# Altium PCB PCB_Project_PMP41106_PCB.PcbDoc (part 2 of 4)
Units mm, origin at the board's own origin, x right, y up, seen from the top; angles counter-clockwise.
Board outline 190 x 100 mm, 2 copper layers (Top Layer, Bottom Layer), stack 1.646 mm thick; 219 components, 122 nets, 541 pads, 61 vias.
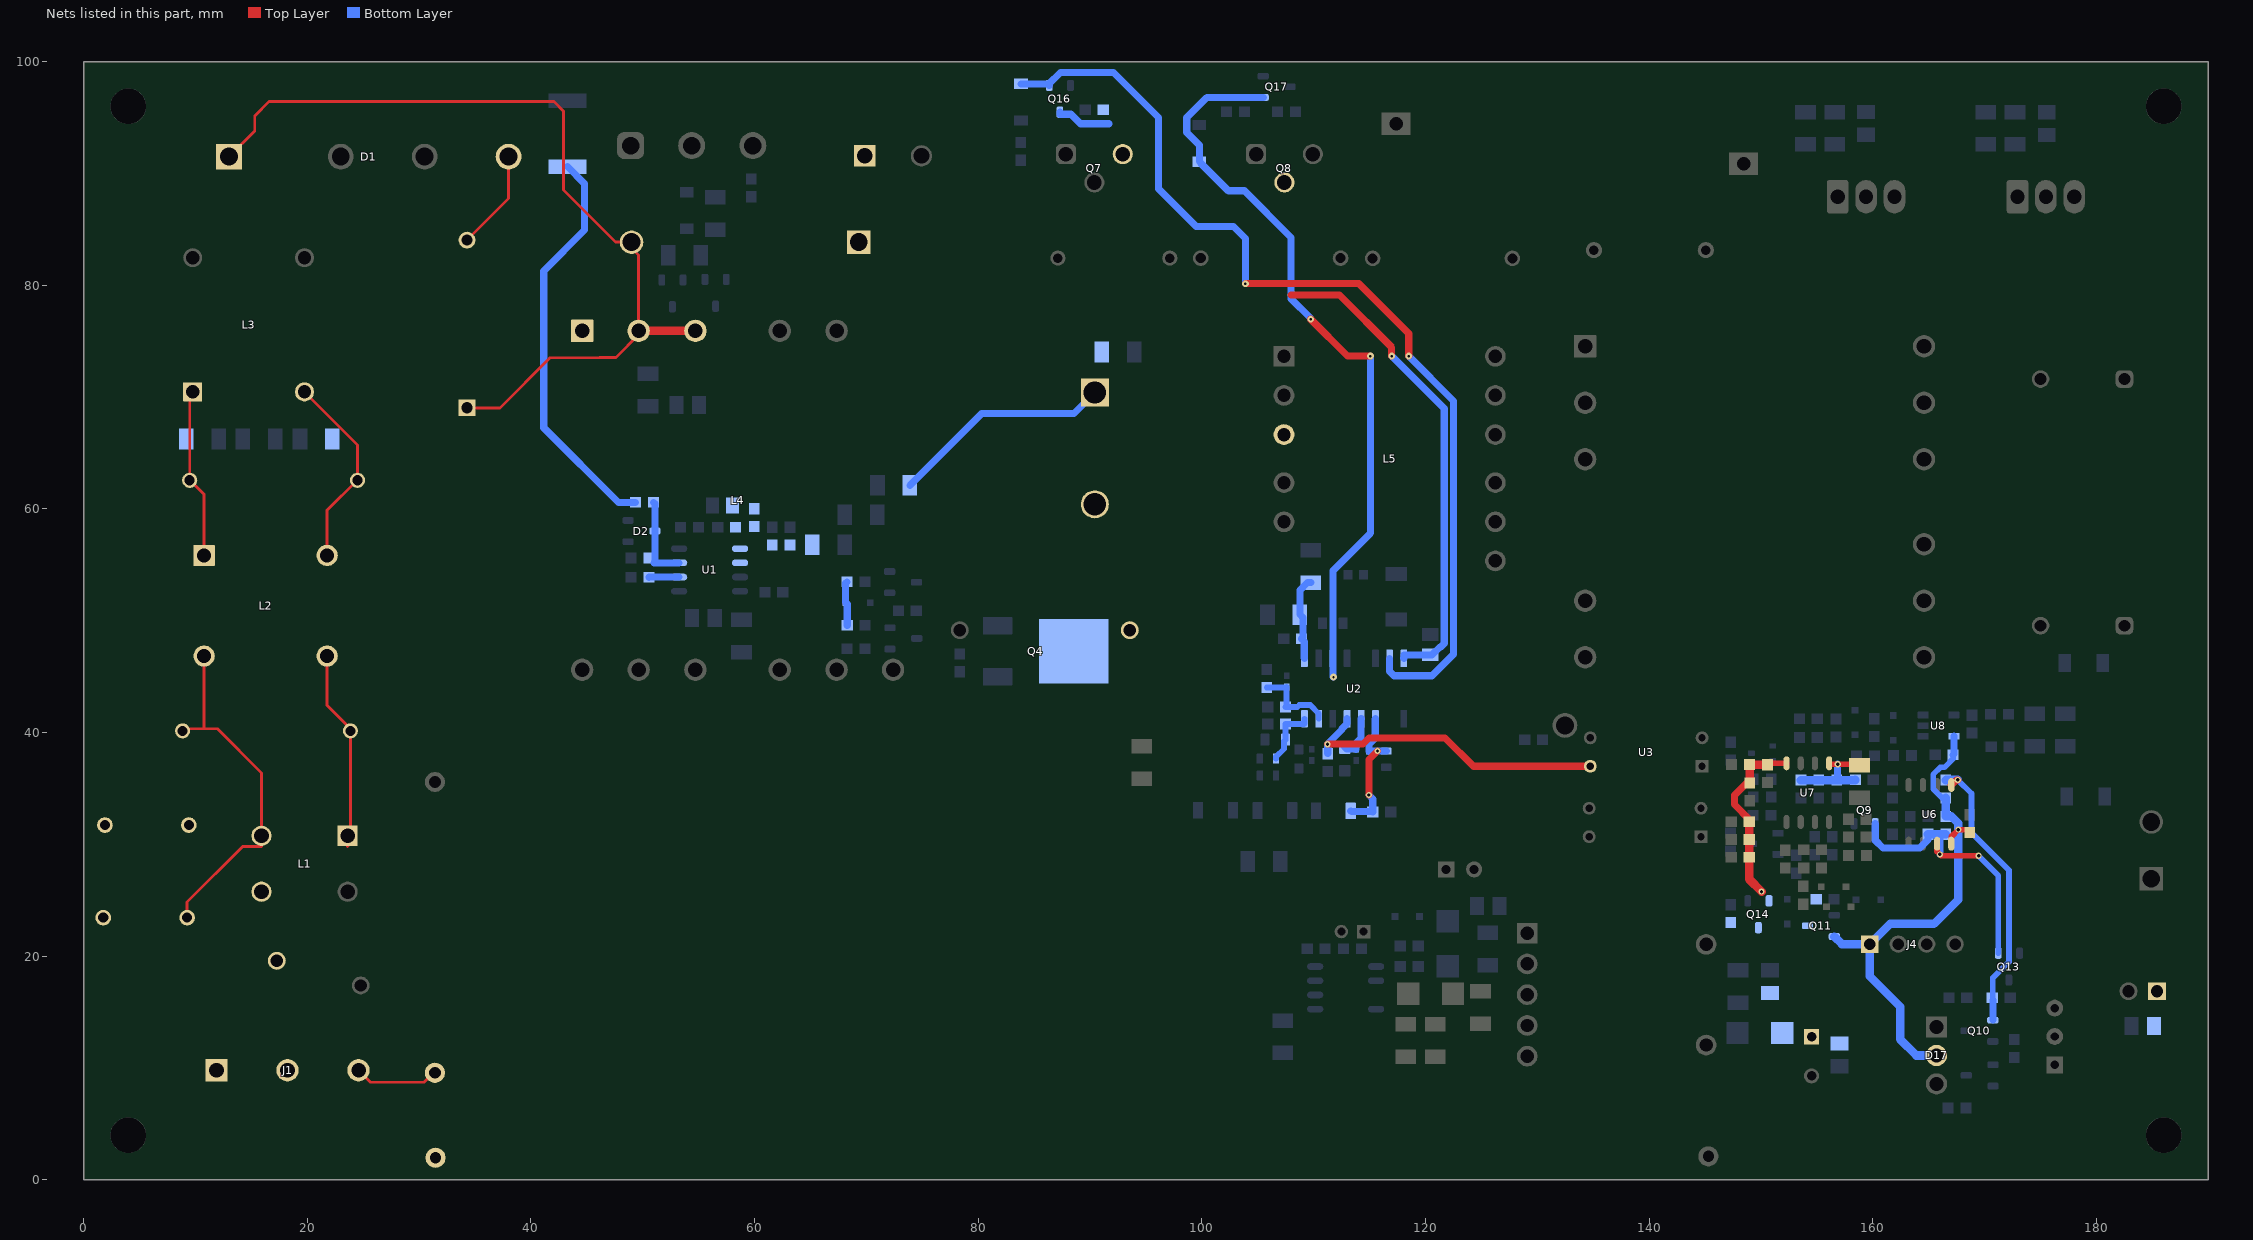
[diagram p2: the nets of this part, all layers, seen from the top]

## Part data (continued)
C6: library part CMP-0007172-4, "CAP, CERM, 1000 pF, 50 V, +/- 1%, C0G/NP0, 0603", Cap_Case=0603, Manufacturer=MuRata, Supplier Part Number 1=490-6377-1-ND, TempCo=C0G/NP0, Tolerance_%=1%, Value1=Unknown, Value2=50V, ValueDisplayed=1000pF
C7: library part CMP-0007870-2, "CAP, CERM, 4.7 uF, 25 V, +/- 10%, X7R, 0805", Cap_Case=0805, Manufacturer=TDK, PartNumber=C2012X7R1E475K125AB, Supplier Part Number 1=445-5972-1-ND, TempCo=X7R, Tolerance_%=10%, Value1=Unknown, Value2=25V, ValueDisplayed=4.7uF
C8: library part CMP-0006867-4, "CAP, CERM, 0.68uF, 25 V, +/- 10%, X7R, 0603", Cap_Case=0603, Manufacturer=Kemet, Supplier Part Number 1=399-7376-1-ND, TempCo=X7R, Tolerance_%=10%, Value1=Unknown, Value2=25V, ValueDisplayed=1uF
C9: library part CMP-0007203-4, "CAP, CERM, 270 pF, 50 V, +/- 5%, C0G/NP0, 0603", Cap_Case=0603, Manufacturer=MuRata, Supplier Part Number 1=490-1437-1-ND, TempCo=C0G/NP0, Tolerance_%=5%, Value1=Unknown, Value2=50V, ValueDisplayed=270pF
C10: library part CMP-0007877-2, "CAP, CERM, 2.2 uF, 50 V, +/- 10%, X7R, 0805", Cap_Case=0805, Manufacturer=TDK, Supplier Part Number 1=445-5968-1-ND, TempCo=X7R, Tolerance_%=10%, Value1="0.00366 ohm", Value2=50V, ValueDisplayed=2.2uF
C11: library part CMP-0009979-2, "CAP, AL, 220 uF, 450 V, +/- 20%, TH", Cap_Case=25x40mm, Manufacturer=Rubycon, Supplier Part Number 1=1189-1974-ND, Tolerance_%=20%, Value1=Unknown, Value2=450V, ValueDisplayed=220uF
C12: library part CMP-0007424-4, "CAP, CERM, 0.47 uF, 25 V, +/- 10%, X7R, 0603", Cap_Case=0603, Manufacturer=MuRata, Supplier Part Number 1=490-3291-1-ND, TempCo=X7R, Tolerance_%=10%, Value1=Unknown, Value2=25V, ValueDisplayed=0.47uF
C13: library part CMP-0006249-2, "CAP, CERM, 220 pF, 50 V, +/- 1%, C0G/NP0, 0402", Cap_Case=0402, Manufacturer=TDK, Supplier Part Number 1=445-7015-1-ND, TempCo=C0G/NP0, Tolerance_%=1%, Value1=Unknown, Value2=50V, ValueDisplayed=220pF
C14: library part CMP-0012506-3, "CAP, Film, 0.022 uF, 630 V, +/- 3%, TH", Cap_Case=12.5x6.2x10.5mm, Manufacturer=Panasonic, Supplier Part Number 1=P12125-ND, Tolerance_%=3%, Value1=Unknown, Value2=630V, ValueDisplayed=0.022uF
C15 C17: library part CMP-0089823-1, "2.2µF ±10% 35V Ceramic Capacitor X7R 0805 (2012 Metric)", Digikey Part Number=445-6963-1-ND, Manufacturer=TDK, Mouser Part Number=810-CGA4J1X7R1V225K, Operating Temperature Range="-55°C to +125°C", TempCo=15%, Temperature Characteristic=X7R, Tolerance_%=10%, ValueDisplayed=2.2uF
C16: library part CMP-0006609-2, "CAP, CERM, 2200 pF, 25 V, +/- 10%, X5R, 0402", Cap_Case=0402, Manufacturer=MuRata, Supplier Part Number 1=GRM155R61E222KA01D-ND, TempCo=X5R, Tolerance_%=10%, Value1=Unknown, Value2=25V, ValueDisplayed=2200pF
C18: library part CMP-0007573-2, "CAP, CERM, 2.2 uF, 25 V, +/- 10%, X7R, 0805", Cap_Case=0805, Manufacturer=AVX, Supplier Part Number 1=478-5719-1-ND, TempCo=X7R, Tolerance_%=10%, Value1=Unknown, Value2=25V, ValueDisplayed=2.2uF
C19: library part CMP-0006699-2, "CAP, CERM, 1000 pF, 100 V, +/- 10%, X7R, 0402", Cap_Case=0402, Manufacturer=MuRata, Supplier Part Number 1=GRM155R72A102KA01D-ND, TempCo=X7R, Tolerance_%=10%, Value1=Unknown, Value2=100V, ValueDisplayed=1000pF
C20: library part CMP-0006922-4, "CAP, CERM, 3300 pF, 50 V, +/- 10%, X7R, 0603", Cap_Case=0603, Manufacturer=Kemet, Supplier Part Number 1=399-1086-1-ND, TempCo=X7R, Tolerance_%=10%, Value1=Unknown, Value2=50V, ValueDisplayed=3300pF
C21: library part CMP-0861060-1, "CAP, CERM, 1000 pF, 50 V,+/- 5%, X7R, 0402", Cap_Case=0402, Manufacturer=AVX, TempCo=X7R, Tolerance_%=5%, Value2=50V, ValueDisplayed=1000pF
C22 C23: library part CMP-0012312-3, "CAP, Film, 0.022 uF, 800 V, +/- 3%, TH", Cap_Case=15x7x12.5, Manufacturer="Panasonic Electronic Components", Supplier Part Number 1=P14259-ND, Tolerance_%=10%, Value1=Unknown, Value2=800V, ValueDisplayed=0.022uF
C24: library part CMP-0008884-2, "CAP, CERM, 100 pF, 630 V, +/- 5%, C0G/NP0, 1206", Cap_Case=1206, Manufacturer=MuRata, PartNumber=GRM31A5C2J101JW01D, Supplier Part Number 1=490-5273-1-ND, TempCo=C0G/NP0, Tolerance_%=5%, Value1=Unknown, Value2=630V, ValueDisplayed=100pF
C27: library part CMP-0007415-4, "CAP, CERM, 0.22 uF, 25 V, +/- 10%, X7R, 0603", Cap_Case=0603, Manufacturer=MuRata, Supplier Part Number 1=490-3290-1-ND, TempCo=X7R, Tolerance_%=10%, Value1=Unknown, Value2=25V, ValueDisplayed=0.22uF
C28: library part CMP-0006959-4, "CAP, CERM, 680 pF, 50 V, +/- 5%, C0G/NP0, 0603", Cap_Case=0603, Manufacturer=MuRata, Supplier Part Number 1=490-1427-1-ND, TempCo=C0G/NP0, Tolerance_%=5%, Value1=Unknown, Value2=50V, ValueDisplayed=100pF
C29 C32 C35 C36 C43 C45 C47 C57: library part CMP-0006979-5, "CAP, CERM, 0.1 uF, 25 V, +/- 10%, X7R, 0603", Cap_Case=0603, Manufacturer=Kemet, Supplier Part Number 1=399-5345-1-ND, TempCo=X7R, Tolerance_%=10%, Value1=Unknown, Value2=25V, ValueDisplayed=0.1uF
C30: library part CMP-0078358-1, "CAP, CERM, 2200 pF, X1 400 VAC/Y1 400 VAC, +/- 20%, Y5V, D9xL13mm", Cap_Case=9x13mm, Manufacturer=Kemet, Supplier Part Number 1=399-9487-1-ND, TempCo=Y5V, Tolerance_%=20%, ValueDisplayed=2200pF
C31: library part CMP-0006978-4, "CAP, CERM, 0.01 uF, 50 V, +/- 10%, X7R, 0603", Cap_Case=0603, Manufacturer=Kemet, Supplier Part Number 1=399-5346-1-ND, TempCo=X7R, Tolerance_%=10%, Value1=Unknown, Value2=50V, ValueDisplayed=0.01uF
C33: library part CMP-0006846-4, "CAP, CERM, 1000 pF, 25 V, +/- 10%, C0G/NP0, 0603", Cap_Case=0603, Manufacturer=Kemet, Supplier Part Number 1=399-7833-1-ND, TempCo=C0G/NP0, Tolerance_%=10%, Value1="0 ohm", Value2=25V, ValueDisplayed=1000pF
C34: library part CMP-0006986-4, "CAP, CERM, 470 pF, 50 V, +/- 10%, X7R, 0603", Cap_Case=0603, Manufacturer=Kemet, Supplier Part Number 1=399-5338-1-ND, TempCo=X7R, Tolerance_%=10%, Value1=Unknown, Value2=50V, ValueDisplayed=470pF
C37 C38: library part CMP-0074690-1, "CAP, CERM, 100 pF, 250 V,+/- 5%, C0G/NP0, 0805", Cap_Case=0805, Manufacturer="Samsung Electro-Mechanics", Supplier Part Number 1=1276-6631-1-ND, TempCo=C0G/NP0, Tolerance_%=5%, Value2=250V, ValueDisplayed=100pF
C39 C41: library part CMP-0077674-1, "CAP, AL, 680 µF, 80 V, +/- 20%, TH", Cap_Case=16x25mm, Manufacturer="Panasonic Electronic Components", Supplier Part Number 1=PCE5219-ND, Tolerance_%=20%, Value2=80V, ValueDisplayed=680µF
C40: library part CMP-0007042-4, "CAP, CERM, 0.22 uF, 25 V, +/- 10%, X7R, 0603", Cap_Case=0603, Manufacturer=TDK, Supplier Part Number 1=445-5191-1-ND, TempCo=X7R, Tolerance_%=10%, Value1=Unknown, Value2=25V, ValueDisplayed=0.22uF
C42: library part CMP-0006977-4, "CAP, CERM, 0.01 uF, 100 V, +/- 10%, X7R, 0603", Cap_Case=0603, Manufacturer=Kemet, Supplier Part Number 1=399-5347-1-ND, TempCo=X7R, Tolerance_%=10%, Value1=Unknown, Value2=100V, ValueDisplayed=0.01uF
C44 C46: library part CMP-0008970-2, "CAP, CERM, 1 uF, 100 V, +/- 10%, X7R, 1206", Cap_Case=2220, Manufacturer=MuRata, Supplier Part Number 1=490-3909-1-ND, TempCo=X7R, Tolerance_%=10%, Value1=Unknown, Value2=100V, ValueDisplayed=1uF
C48: library part CMP-0010292-1, "CAP, AL, 22 uF, 25 V, +/- 20%, TH", Cap_Case=5x5, Manufacturer=Rubycon, Supplier Part Number 1=25ML22MEFC5X5-ND, Tolerance_%=20%, Value1=Unknown, Value2=25V, ValueDisplayed=22uF
C49: library part CMP-0010339-1, "CAP, AL, 100 uF, 25 V, +/- 20%, 0.13 ohm, TH", Cap_Case=6.3x11.2, Manufacturer=Panasonic, Supplier Part Number 1=P12924-ND, Tolerance_%=20%, Value1="0.13 ohm", Value2=25V, ValueDisplayed=100uF
C50: library part CMP-0860549-1, "CAP, CERM, 1 µF, 25 V,+/- 10%, X7R, 0603", Cap_Case=0603, Manufacturer=TDK, TempCo=X7R, Tolerance_%=10%, Value2=25V, ValueDisplayed=1µF
C51 C53: library part CMP-0007534-2, "CAP, CERM, 470 pF, 100 V, +/- 5%, C0G/NP0, 0805", Cap_Case=0805, Manufacturer=AVX, Supplier Part Number 1=478-1288-1-ND, TempCo=C0G/NP0, Tolerance_%=5%, Value1="0.159 ohm", Value2=100V, ValueDisplayed=470pF
C52 C58: library part CMP-0008912-2, "CAP, CERM, 2200 pF, 630 V, +/- 10%, X7R, 1206", Cap_Case=1206, Manufacturer=MuRata, Supplier Part Number 1=490-3508-1-ND, TempCo=X7R, Tolerance_%=10%, Value1=Unknown, Value2=630V, ValueDisplayed=2200pF
C54: library part CMP-0010404-1, "CAP, AL, 220 uF, 25 V, +/- 20%, TH", Cap_Case=8x11.5, Manufacturer=Chemi-Con, Supplier Part Number 1=565-1674-ND, Tolerance_%=20%, Value1=Unknown, Value2=25V, ValueDisplayed=220uF
C55 C56: library part CMP-0008136-2, "CAP, CERM, 1 uF, 25 V, +/- 10%, X5R, 0805", Cap_Case=0805, Manufacturer=MuRata, Supplier Part Number 1=490-1700-1-ND, TempCo=X5R, Tolerance_%=10%, Value1="0.009 ohm", Value2=25V, ValueDisplayed=1uF
CY1 CY2: "CAP, CERM, 2200 pF, 300 V, +/- 20%, E, TH, 2- Leads, Body 9x7mm, Pin Spacing 7.5mm", Cap_Case=9x7x9mm, Manufacturer=MuRata, Supplier Part Number 1=DE6E3KJ222MN3A-ND, TempCo=E, Tolerance_%=20, Value1=Unknown, Value2=300V, ValueDisplayed=2200pF
D1: library part CMP-0082068-2, "Diode, P-N-Bridge, 600 V, 25 A, TH", Manufacturer="Micro Commercial Components", Value1=25A, Value2=1.05V
D2: library part CMP-0029178-2, "Diode, Switching, 250 V, 0.4 A, SOT-23", Manufacturer="ON Semiconductor", Value1=0.4A, Value2=1.25V
D3: library part CMP-0029223-3, "Diode, Switching-Bridge, 600 V, 3 A, TH", Manufacturer=Vishay-Semiconductor, Value1=3A, Value2=1.2V
D4: library part CMP-0029001-2, "Diode, Ultrafast, 100 V, 0.15 A, SOD-123", Manufacturer="Diodes Inc.", Value1=0.15A, Value2=1.25V
D5: library part CMP-0028618-2, "Diode, Schottky, 600 V, 4 A, TH", Manufacturer=Cree, Value1=4A, Value2=1.8V
D6: library part CMP-0085739-1, "Diode, Zener, 5.1 V, 300 mW, SOD-323", Manufacturer="ON Semiconductor", Power_W=300mW, Value1=0.3W
D7 D8: library part CMP-0079240-2, "Diode, Schottky, 30 V, 1 A, AEC-Q101, SOD-123", Manufacturer=Nexperia, Value1=1A, Value2=0.56V
D9: library part CMP-0029162-2, "Diode, Ultrafast, 600 V, 1 A, AEC-Q101, SMAF", Manufacturer="Fairchild Semiconductor", Value1=1A, Value2=1.7V
D10: library part CMP-0028627-2, "Diode, Schottky, 30 V, 0.2 A, SOT-323", Manufacturer="Micro Commercial Components", Value1=0.2A, Value2=1V
D11 D12: library part CMP-0028764-3, "Diode, Schottky, 200 V, 20 A, TH", Manufacturer="Taiwan Semiconductor Corporation", Value1=20A, Value2=0.99V
D13 D14 D15 D16: library part CMP-0028449-2, "Diode, Schottky, 30 V, 0.2 A, SOD-323", Manufacturer="Diodes Inc.", Value1=0.2A, Value2=1V
D17: library part CMP-0087778-1, "LED GRN/RED DIFF 5MM ROUND T/H", Color="Green, Red", Manufacturer="Marktech Optoelectronics"
D18: library part CMP-0085741-1, "Diode, Zener, 5.6 V, 300 mW, SOD-323", Manufacturer="ON Semiconductor", Power_W=300mW, Value1=0.3W
D19: library part CMP-0082069-2, "Diode, Switching, 75 V, 0.15 A, SOD-323", Manufacturer="Micro Commercial Components", Value1=0.15A, Value2=1V
D20 D22: library part CMP-0029024-2, "Diode, Ultrafast, 200 V, 1 A, SMA", Manufacturer="Diodes Inc.", Value1=1A, Value2=0.92V
D21: library part CMP-0076882-2, "Diode, Ultrafast, 1000 V, 1 A, SMA", Manufacturer="Diodes Inc.", Value1=1A, Value2=1.7V
D23: library part CMP-0005842-4, "Diode, Zener, 11 V, 300 mW, SOD-323", Manufacturer="NXP Semiconductor", Power_W=300mW, Value1=0.3W
F1: library part CMP-0079917-2, "Fuse, 10 A, 250 VAC, TH", Irating_A=10A, Manufacturer=Littelfuse, PartNumber=0216008.MXEP, Supplier Part Number 1=F3603-ND
H1: library part 7106DG
H2: library part 7106DG, PartNumber=40mm*40mm
I_OPTO: library part CMP-0055149-2, "Test Point, Multipurpose, White, TH", Color=White, Manufacturer="Keystone Electronics", Supplier Part Number 1=36-5012-ND
J1: library part CMP-0055483-1, "Terminal Block, 3x1, 6.35 mm, TH", Manufacturer="Phoenix Contact", Supplier Part Number 1=277-1270-ND
J2: library part CMP-0054770-2, "Receptacle, 5.08mm, 2x1, Brass, TH", Color=Green, Current_A=10A, Manufacturer="Wurth Elektronik", Supplier Part Number 1=732-2749-ND, Voltage_V=300V
J3: library part CMP-0055242-1, "Header(shrouded), 2.54mm, 2x1, Gold, TH", Color=Black, Current_A=3A, Manufacturer=Molex, Supplier Part Number 1=WM4800-ND, Voltage_V=250V
J4: library part CMP-0055331-1, "Header, 2.54mm, 4x1, Tin, TH", Color=Black, Current_A=4A, Manufacturer=Molex, Supplier Part Number 1=WM50016-04-ND, Voltage_V=250V
L1: library part CMP-0013095-2, "Coupled inductor, 8.5 A, 0.0055 ohm, TH", Manufacturer="Wurth Elektronik", Supplier Part Number 1=732-3246-ND
L2: library part CMP-0089807-1, "8.3mH @ 10kHz 2 Line Common Mode Choke Through Hole DCR 12mOhm", Manufacturer="YAXIN ELECTRONICS", Operating Temperature Range=to, Test Frequency=10kHz, Tolerance_%=30%
L3: library part CMP-0013082-2, "Coupled inductor, 7 mH, 7 A, 0.02 ohm, TH", Manufacturer="Wurth Elektronik", Supplier Part Number 1=732-5589-ND, ValueDisplayed=7mH
L4: library part CMP-0120779-1, "PFC INDUCTOR", Manufacturer=Bourns, Operating Temperature Range="-40°C to +125°C", Test Frequency=100kHz, Tolerance_%=10%
L5: library part CMP-0120782-1, "LLC INDUCTOR", Manufacturer=Bourns, Operating Temperature Range="-40°C to +125°C", Test Frequency=100Hz, Tolerance_%=10%
LOGO1: library part CMP-0074835-1, "IEC 61010-1 High Voltage Warning"
LOGO2: library part CMP-0074837-1, "IEC 61010-1 Hot Surface Warning"
Logo3: library part CMP-0074847-1, "FCC_disclaimer"
Logo4: library part CMP-0074769-1
Q1: library part CMP-0001178-3, "MOSFET, N-CH, 600 V, 37 A, TO-247", Alternate Manufacturer=None, Manufacturer="Infineon Technologies", Supplier Part Number 1=IPW60R080P7XKSA1-ND, Value2="51 nC"
Q2: library part CMP-0000461-2, "Transistor, NPN, 40 V, 0.6 A, SOT-23", Manufacturer="ON Semiconductor", Supplier Part Number 1=MMBT2222ALT1GOSCT-ND, Value1="0.6 A"
Q3: library part CMP-0000344-2, "Transistor, PNP, 60 V, 0.6 A, SOT-23", Manufacturer="ON Semiconductor", Supplier Part Number 1=MMBT2907ALT1GOSCT-ND, Value1="0.6 A"
Q4: library part CMP-0079238-2, "MOSFET, N-CH, 600 V, 18 A, DPAK", Alternate Manufacturer=None, Manufacturer="Infineon Technologies", Supplier Part Number 1=IPD60R180P7SAUMA1CT-ND, Value1="180m ohm", Value2="25 nC"
Q5: library part CMP-0000325-2, "Transistor, PNP, 40 V, 0.2 A, SOT-23", Manufacturer="ON Semiconductor", Supplier Part Number 1=MMBT3906LT1GOSCT-ND, Value1="0.2 A", Value2=300
Q6 Q11 Q14: library part CMP-0000419-2, "Transistor, NPN, 40 V, 0.2 A, SOT-23", Manufacturer="ON Semiconductor", Supplier Part Number 1=MMBT3904LT1GOSCT-ND, Value1="0.2 A", Value2=300
Q7 Q8: library part CMP-0079306-2, "MOSFET, N-CH, 600 V, 8 A, TO-220FP", Alternate Manufacturer=None, Manufacturer="Infineon Technologies", Value1="? ohm", Value2="28 nC"
Q9 Q10 Q12 Q13: library part CMP-0000769-1, "MOSFET, N-CH, 60 V, 0.17 A, SOT-23", Alternate Manufacturer=None, Manufacturer="Diodes Inc.", Supplier Part Number 1=2N7002-FDICT-ND, Value1=7, Value2="223 nC"
Q15: library part CMP-0000425-2, "Transistor, NPN, 40 V, 0.5 A, TO-92AP", Manufacturer="Micro Commercial Components", Supplier Part Number 1=2N4401-APCT-ND, Value1="0.5 A", Value2=300
Q16 Q17: library part CMP-0000317-2, "Transistor, PNP, 30 V, 0.1 A, SOT-23", Manufacturer="Diodes Inc.", Supplier Part Number 1=BC858C-7-F-ND, Value1="0.1 A", Value2=600
R1 R2 R3: library part CMP-0018205-2, "RES, 330 k, 1%, 0.25 W, 1206", Manufacturer="Yageo America", Power_W=250mW, Supplier Part Number 1=311-330KFRCT-ND, TempCo="100 ppm/C", Tolerance_%=1%, Value2=0.25W, Value_Code=330k
R4 R18 R28 R74: library part CMP-0018759-2, "RES, 0, 5%, 0.25 W, 1206", Manufacturer="Yageo America", Power_W=250mW, Supplier Part Number 1=311-0.0ERCT-ND, TempCo="200 ppm/C", Tolerance_%=5%, Value2=0.25W, Value_Code=0000, ValueDisplayed=0
R5: library part CMP-0022918-5, "RES, 220, 1%, 0.1 W, 0603", Manufacturer=Yageo, Power_W=100mW, Supplier Part Number 1=311-220HRCT-ND, TempCo="100 ppm/C", Tolerance_%=1%, Value2=0.1W, Value_Code=220R, ValueDisplayed=220
R6: library part CMP-0022913-5, "RES, 21.5 k, 1%, 0.1 W, 0603", Manufacturer=Yageo, Power_W=100mW, Supplier Part Number 1=311-21.5KHRCT-ND, TempCo="100 ppm/C", Tolerance_%=1%, Value2=0.1W, Value_Code=21k5, ValueDisplayed=21.5k
R7: library part CMP-0015773-2, "RES, 0.02, 1%, 2 W, 2512", Manufacturer="Stackpole Electronics Inc", Power_W=2W, Supplier Part Number 1=CSRN2512FK20L0CT-ND, TempCo="200 ppm/C", Tolerance_%=1%, Value_Code=R020, ValueDisplayed=0.02
R8 R20 R33 R34 R42 R44 R52 R84 R86: library part CMP-0022746-5, "RES, 10.0 k, 1%, 0.1 W, 0603", Manufacturer=Yageo, Power_W=100mW, Supplier Part Number 1=311-10.0KHRCT-ND, TempCo="100 ppm/C", Tolerance_%=1%, Value2=0.1W, Value_Code=10k0, ValueDisplayed=10.0k
R9 R12 R13: library part CMP-0018270-2, "RES, 3.30, 1%, 0.25 W, 1206", Manufacturer="Yageo America", Power_W=250mW, Supplier Part Number 1=311-3.30FRCT-ND, TempCo="200 ppm/C", Tolerance_%=1%, Value2=0.25W, Value_Code=3R30, ValueDisplayed=3.30
R10: library part CMP-0086298-1, "RES, 12.4 k, 1%, 0.1 W, AEC-Q200 Grade 0, 0603", Manufacturer=Panasonic, PartNumber=ERJ-3EKF1242V, Power_W=100mW, TempCo="100 ppm/C", Tolerance_%=1%, Value2=0.1W, Value_Code=12k4, ValueDisplayed=12.4k
R11 R67 R70: library part CMP-0022751-4, "RES, 10.0, 1%, 0.1 W, 0603", Manufacturer=Yageo, Power_W=100mW, Supplier Part Number 1=311-10.0HRCT-ND, TempCo="100 ppm/C", Tolerance_%=1%, Value2=0.1W, Value_Code=10R0, ValueDisplayed=10.0
R14 R15 R16: library part CMP-0018027-2, "RES, 1.00 M, 1%, 0.25 W, 1206", Manufacturer="Yageo America", Power_W=250mW, Supplier Part Number 1=311-1.00MFRCT-ND, TempCo="100 ppm/C", Tolerance_%=1%, Value2=0.25W, Value_Code=1M00, ValueDisplayed=1.00M
R17: library part CMP-0023073-5, "RES, 39.0 k, 1%, 0.1 W, 0603", Manufacturer=Yageo, Power_W=100mW, Supplier Part Number 1=311-39.0KHRCT-ND, TempCo="100 ppm/C", Tolerance_%=1%, Value2=0.1W, Value_Code=39k0, ValueDisplayed=39.0k
R19 R21 R22 R64: library part CMP-0022735-5, "RES, 100 k, 1%, 0.1 W, 0603", Manufacturer=Yageo, Power_W=100mW, Supplier Part Number 1=311-100KHRCT-ND, TempCo="100 ppm/C", Tolerance_%=1%, Value2=0.1W, Value_Code=100k
R23 R24: library part CMP-0093030-1, "453 kOhms ±0.1% 0.063W, 1/16W Chip Resistor 0603 (1608 Metric) Thin Film", Digikey Part Number=A124752CT-ND, Manufacturer="TE Connectivity", Mouser Part Number=279-RN73C1J453KBTD, Operating Temperature Range="-55°C to +155°C", Part Number=RN73C1J453KBTD, Power_W=63mW, TempCo=10ppm/°C, Tolerance_%=0.1%
R25: library part CMP-0094963-1, "150kΩ ±1% 0.1W 0603 Thick Film Chip Resistor AEC-Q200 compliant", Manufacturer="Stackpole Electronics", Operating Temperature Range="-55°C to +155°C", Part Number=RMCF0603FT150K, Power_W=100mW, TempCo=100ppm/°C, Tolerance_%=1%
R26: library part CMP-0096703-1, "NTC Thermistor 470k 0603 (1608 Metric)", B Tolerance=3%, Digikey Part Number=495-B57371V2474J060CT-ND, Manufacturer=TDK, Mouser Part Number=871-B57371V2474J060, Operating Temperature Range="-55°C to +125°C", Power_W=180mW, Tolerance_%=5%
R27: library part CMP-0022711-2, "RES, 2.20, 1%, 0.1 W, 0603", Manufacturer=Panasonic, Power_W=100mW, Supplier Part Number 1=P2.2AJCT-ND, TempCo="200 ppm/C", Tolerance_%=1%, Value2=0.1W, Value_Code=2R20, ValueDisplayed=2.20
R29 R30: library part CMP-0022926-4, "RES, 22.1, 1%, 0.1 W, 0603", Manufacturer=Yageo, Power_W=100mW, Supplier Part Number 1=311-22.1HRCT-ND, TempCo="100 ppm/C", Tolerance_%=1%, Value2=0.1W, Value_Code=22R1, ValueDisplayed=22.1
R31: library part CMP-0022809-5, "RES, 150, 1%, 0.1 W, 0603", Manufacturer="Yageo America", Power_W=250mW, Supplier Part Number 1=311-221FRCT-ND, TempCo="100 ppm/C", Tolerance_%=1%, Value2=0.25W, Value_Code=221R, ValueDisplayed=221
R32 R35: library part CMP-0022342-4, "RES, 340 k, 1%, 0.1 W, AEC-Q200 Grade 0, 0603", Manufacturer=Vishay-Dale, PartNumber=CRCW0603340KFKEA, Power_W=100mW, Supplier Part Number 1=541-340KHCT-ND, TempCo="100 ppm/C", Tolerance_%=1%, Value2=0.1W, Value_Code=340k
R36: library part CMP-0023167-5, "RES, 51.0 k, 1%, 0.1 W, 0603", Manufacturer=Yageo, Power_W=100mW, Supplier Part Number 1=311-51.0KHRCT-ND, TempCo="100 ppm/C", Tolerance_%=1%, Value2=0.1W, Value_Code=51k0, ValueDisplayed=51.0k
R37: library part CMP-0022072-4, "RES, 160 k, 1%, 0.1 W, AEC-Q200 Grade 0, 0603", Manufacturer=Vishay-Dale, PartNumber=CRCW0603160KFKEA, Power_W=100mW, Supplier Part Number 1=541-160KHCT-ND, TempCo="100 ppm/C", Tolerance_%=1%, Value2=0.1W, Value_Code=160k
R38: library part CMP-0025885-5, "RES, 0, 5%, 0.1 W, 0603", Manufacturer="Vishay Draloric", Power_W=100mW, Supplier Part Number 1=541-1784-1-ND, TempCo="100 ppm/C", Tolerance_%=1%, Value2=0.1W, Value_Code=10k0, ValueDisplayed=10.0k
R39 R41 R56 R82: library part CMP-0023091-5, "RES, 3.00 k, 1%, 0.1 W, 0603", Manufacturer=Yageo, Power_W=100mW, Supplier Part Number 1=311-3.00KHRCT-ND, TempCo="100 ppm/C", Tolerance_%=1%, Value2=0.1W, Value_Code=3k00, ValueDisplayed=3.00k
R40: library part CMP-0022746-5, "RES, 10.0 k, 1%, 0.1 W, 0603", Manufacturer=Yageo, Power_W=100mW, Supplier Part Number 1=311-6.04KHRCT-ND, TempCo="100 ppm/C", Tolerance_%=1%, Value2=0.1W, Value_Code=6k04, ValueDisplayed=6.04k
R43: library part CMP-0022909-4, "RES, 210 k, 1%, 0.1 W, 0603", Manufacturer=Yageo, PartNumber=RC0603FR-07210KL, Power_W=100mW, Supplier Part Number 1=311-210KHRCT-ND, TempCo="100 ppm/C", Tolerance_%=1%, Value2=0.1W, Value_Code=210k
R45: library part CMP-0023249-5, "RES, 6.34 k, 1%, 0.1 W, 0603", Manufacturer=Yageo, PartNumber=RC0603FR-076K34L, Power_W=100mW, Supplier Part Number 1=311-6.34KHRCT-ND, TempCo="100 ppm/C", Tolerance_%=1%, Value2=0.1W, Value_Code=6k34, ValueDisplayed=6.34k
R46: library part CMP-0023279-5, "RES, 7.50 k, 1%, 0.1 W, 0603", Manufacturer=Yageo, Power_W=100mW, Supplier Part Number 1=311-7.50KHRCT-ND, TempCo="100 ppm/C", Tolerance_%=1%, Value2=0.1W, Value_Code=7k50, ValueDisplayed=7.50k
R47 R58: library part CMP-0023198-5, "RES, 5.10 k, 1%, 0.1 W, 0603", Manufacturer=Yageo, Power_W=100mW, Supplier Part Number 1=311-5.10KHRCT-ND, TempCo="100 ppm/C", Tolerance_%=1%, Value2=0.1W, Value_Code=5k10, ValueDisplayed=5.10k
R48 R49 R50 R51 R75 R81: library part CMP-0017851-2, "RES, 10.0, 1%, 0.25 W, 1206", Manufacturer="Yageo America", Power_W=250mW, Supplier Part Number 1=311-10.0FRCT-ND, TempCo="200 ppm/C", Tolerance_%=1%, Value2=0.25W, Value_Code=10R0, ValueDisplayed=10.0
R53: library part CMP-0023239-5, "RES, 68.0 k, 1%, 0.1 W, 0603", Manufacturer=Yageo, Power_W=100mW, Supplier Part Number 1=311-68.0KHRCT-ND, TempCo="100 ppm/C", Tolerance_%=1%, Value2=0.1W, Value_Code=68k0, ValueDisplayed=68.0k
R54: library part CMP-0025927-5, "RES, 4.7 k, 5%, 0.1 W, 0603", Manufacturer=Yageo, Power_W=100mW, Supplier Part Number 1=311-2.40KHRCT-ND, TempCo="100 ppm/C", Tolerance_%=1%, Value2=0.1W, Value_Code=2k40, ValueDisplayed=2.40k
R55: library part CMP-0022857-5, "RES, 191, 1%, 0.1 W, 0603", Manufacturer=Yageo, PartNumber=RC0603FR-07191RL, Power_W=100mW, Supplier Part Number 1=311-191HRCT-ND, TempCo="100 ppm/C", Tolerance_%=1%, Value2=0.1W, Value_Code=191R, ValueDisplayed=191
R57: library part CMP-0023081-5, "RES, 3.30 k, 1%, 0.1 W, 0603", Manufacturer=Yageo, PartNumber=RC0603FR-073K3L, Power_W=100mW, Supplier Part Number 1=311-3.30KHRCT-ND, TempCo="100 ppm/C", Tolerance_%=1%, Value2=0.1W, Value_Code=3k30, ValueDisplayed=3.30k
R59: library part CMP-0023141-5, "RES, 499, 1%, 0.1 W, 0603", Manufacturer=Yageo, Power_W=100mW, Supplier Part Number 1=311-499HRCT-ND, TempCo="100 ppm/C", Tolerance_%=1%, Value2=0.1W, Value_Code=499R, ValueDisplayed=499
R60: library part CMP-0025919-5, "RES, 3.6 k, 5%, 0.1 W, 0603", Manufacturer=Yageo, Power_W=100mW, Supplier Part Number 1=311-2.00KHRCT-ND, TempCo="100 ppm/C", Tolerance_%=1%, Value2=0.1W, Value_Code=2k00, ValueDisplayed=2.00k
R61 R63: library part CMP-0022908-4, "RES, 20.0, 1%, 0.1 W, 0603", Manufacturer=Yageo, Power_W=100mW, Supplier Part Number 1=311-20.0HRCT-ND, TempCo="100 ppm/C", Tolerance_%=1%, Value2=0.1W, Value_Code=20R0, ValueDisplayed=20.0
R62: library part CMP-0022666-4, "RES, 9.31 k, 1%, 0.1 W, AEC-Q200 Grade 0, 0603", Manufacturer=Vishay-Dale, PartNumber=CRCW06039K31FKEA, Power_W=100mW, Supplier Part Number 1=541-9.31KHCT-ND, TempCo="100 ppm/C", Tolerance_%=1%, Value2=0.1W, Value_Code=9k31, ValueDisplayed=9.31k
R65: library part CMP-0022042-4, "RES, 13.0 k, 1%, 0.1 W, AEC-Q200 Grade 0, 0603", Manufacturer=Vishay-Dale, PartNumber=CRCW060313K0FKEA, Power_W=100mW, Supplier Part Number 1=541-13.0KHCT-ND, TempCo="100 ppm/C", Tolerance_%=1%, Value2=0.1W, Value_Code=13k0, ValueDisplayed=13.0k
R66 R83: library part CMP-0022895-5, "RES, 1.00 k, 1%, 0.1 W, 0603", Manufacturer=Yageo, Power_W=100mW, Supplier Part Number 1=311-1.00KHRCT-ND, TempCo="100 ppm/C", Tolerance_%=1%, Value2=0.1W, Value_Code=1k00, ValueDisplayed=1.00k
R68 R69: library part CMP-0018567-2, "RES, 0.006, 1%, 0.5 W, 1206", Manufacturer=Vishay-Dale, PartNumber=WSL12066L000FEA18, Power_W=500mW, Supplier Part Number 1=WSLD-.006CT-ND, TempCo="110 ppm/C", Tolerance_%=1%, Value2=0.5W, Value_Code=6L000, ValueDisplayed=0.006
R71 R72: library part CMP-0023163-5, "RES, 510, 1%, 0.1 W, 0603", Manufacturer=Yageo, Power_W=100mW, Supplier Part Number 1=311-510HRCT-ND, TempCo="100 ppm/C", Tolerance_%=1%, Value2=0.1W, Value_Code=510R, ValueDisplayed=510
R73: library part CMP-0023086-5, "RES, 3.60 k, 1%, 0.1 W, 0603", Manufacturer=Yageo, Power_W=100mW, Supplier Part Number 1=311-3.60KHRCT-ND, TempCo="100 ppm/C", Tolerance_%=1%, Value2=0.1W, Value_Code=3k60, ValueDisplayed=3.60k
R76: library part CMP-0018060-2, "RES, 200 k, 1%, 0.25 W, 1206", Manufacturer="Yageo America", Power_W=250mW, Supplier Part Number 1=311-200KFRCT-ND, TempCo="100 ppm/C", Tolerance_%=1%, Value2=0.25W, Value_Code=200k
R77: library part CMP-0018061-2, "RES, 200, 1%, 0.25 W, 1206", Manufacturer="Yageo America", Power_W=250mW, Supplier Part Number 1=311-200FRCT-ND, TempCo="100 ppm/C", Tolerance_%=1%, Value2=0.25W, Value_Code=200R, ValueDisplayed=200
R78: library part CMP-0022892-5, "RES, 1.80 k, 1%, 0.1 W, 0603", Manufacturer=Yageo, Power_W=100mW, Supplier Part Number 1=311-1.80KHRCT-ND, TempCo="100 ppm/C", Tolerance_%=1%, Value2=0.1W, Value_Code=1k80, ValueDisplayed=1.80k
R79: library part CMP-0023292-5, "RES, 82.0 k, 1%, 0.1 W, 0603", Manufacturer=Yageo, Power_W=100mW, Supplier Part Number 1=311-82.0KHRCT-ND, TempCo="100 ppm/C", Tolerance_%=1%, Value2=0.1W, Value_Code=82k0, ValueDisplayed=82.0k
R80: library part CMP-0023020-5, "RES, 30.0 k, 1%, 0.1 W, 0603", Manufacturer=Yageo, Power_W=100mW, Supplier Part Number 1=311-30.0KHRCT-ND, TempCo="100 ppm/C", Tolerance_%=1%, Value2=0.1W, Value_Code=30k0, ValueDisplayed=30.0k
R85: library part CMP-0017847-2, "RES, 10.0 k, 1%, 0.25 W, 1206", Manufacturer="Yageo America", Power_W=250mW, Supplier Part Number 1=311-10.0KFRCT-ND, TempCo="100 ppm/C", Tolerance_%=1%, Value2=0.25W, Value_Code=10k0, ValueDisplayed=10.0k
R87: library part CMP-0025929-5, "RES, 51 k, 5%, 0.1 W, 0603", Manufacturer=Yageo, Power_W=100mW, Supplier Part Number 1=311-150KHRCT-ND, TempCo="100 ppm/C", Tolerance_%=1%, Value2=0.1W, Value_Code=150k
R88 R89 R90: library part CMP-0087456-2, "3.3 MOhms ±1% 0.25W, 1/4W Chip Resistor 1206 (3216 Metric) Automotive AEC-Q200, High Voltage Thick Film", Manufacturer="Rohm Semiconductor", Power_W=250mW, TempCo=100ppm/°C, Tolerance_%=1%
R91: library part CMP-0024146-3, "RES, 35.2 k, 0.1%, 0.1 W, 0603", Manufacturer="Yageo America", PartNumber=RT0603BRD0735K2L, Power_W=100mW, TempCo="25 ppm/C", Tolerance_%=0.1%, Value2=0.1W, Value_Code=35k2, ValueDisplayed=35.2k
RF1: library part CMP-0014288-1, "RES, 47, 10%, 2 W, Axial resistor", Manufacturer="TT Electronics/IRC", Power_W=2W, Supplier Part Number 1=985-1022-1-ND, TempCo="100 ppm/C", Tolerance_%=10%, Value_Code=47R0, ValueDisplayed=47
RV1: library part CMP-0002100-2, "Varistor 275V RMS 10MM Radial, TH", Manufacturer=TDK, Supplier Part Number 1=495-1433-ND
T1: library part CMP-0120781-1, "LLC TRANSFORMER", Manufacturer=Bourns, Operating Temperature Range="-40°C to +125°C", Voltage_Isolation_Vrms=3.5kV
T2: library part CMP-0120780-1, "FLYBACK TRANSFORMER", Manufacturer=Bourns, Operating Temperature Range="-40°C to +125°C", Voltage_Isolation_Vrms=3.5kV
U1: library part CMP-0074100-1, "8-PIN CONTINUOUS CONDUCTION MODE (CCM) PFC CONTROLLER, D0008A (SOIC-8)", Alternate Manufacturer="Texas Instruments", Alternate PartNumber=UCC28180D
U2: library part CMP-0095299-2, "750kHz Wide VIN/VOUT Range LLC Controller Optimized for Light Load Efficiency", Manufacturer="Texas Instruments", Max Supply Voltage=18.5V, Operating Temperature Range="-40°C to +150°C", Switching Frequency=30-750kHz
U3 U4: library part CMP-0006173-3, "Optocoupler, 5 kV, 80-160% CTR, TH", Manufacturer="Fairchild Semiconductor", Supplier Part Number 1=FOD817A-ND, Voltage_Isolation_Vrms=5kV
U5: library part CMP-0084729-1, "Programmable Shunt Regulator with Optimized Reference Current, DBZ0003A (SOT-23-3)", Alternate Manufacturer="Texas Instruments"
U6: library part CMP-0075718-1, "GENERAL-PURPOSE LOW-VOLTAGE COMPARATORS, D0008A (SOIC-8)", Alternate Manufacturer="Texas Instruments"
U7: library part CMP-0043697-1, "Dual Operational Amplifier with Internal Reference, 3 to 32 V, -40 to 105 degC, 8-pin SOIC (D8), Green (RoHS & no Sb/Br)", Manufacturer="Texas Instruments", Rating=Catalog, Total Supply Voltage(Max)(+5V is 5, +/-5V is 10)=32, Total Supply Voltage(Min)(+5V is 5, +/-5V is 10)=3
U8: library part CMP-0013064-2, "Low- and High-Side Measurement, Multichannel, Voltage Output, Current-Sense Amplifier, DBV0005A (SOT-5)", Alternate Manufacturer="Texas Instruments"
U9: library part CMP-0067241-2, "700V Flyback Switcher with Constant-Voltage Constant-Current and Primary-side Control, D0007A (SOIC-7)", Alternate Manufacturer="Texas Instruments", Alternate PartNumber=UCC28910D

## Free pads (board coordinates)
  round 3.2 hole 3.2 unplated: 1(4,4) 1(4,96) 1(186,4) 1(186,96)
  round 1.8 hole 1: 1(31.471,1.981) 1(145.288,2.108)

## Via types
v1: diameter 0.559, hole 0.305, Top Layer to Bottom Layer, tented both sides, 50 vias
v2: diameter 0.61, hole 0.203, Top Layer to Bottom Layer, tented both sides, 9 vias
v3: diameter 0.559, hole 0.305, Top Layer to Bottom Layer, 2 vias

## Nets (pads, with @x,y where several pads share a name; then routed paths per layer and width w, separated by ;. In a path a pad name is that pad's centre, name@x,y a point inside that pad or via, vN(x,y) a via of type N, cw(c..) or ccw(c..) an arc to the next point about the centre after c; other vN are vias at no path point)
5V: C43.1 C47.1 D17.2 J4.1 Q11.2 R47.2 R66.1 U6.8 U8.5 | length 46.2
  Top Layer w0.508: U6.8@167.005,30.065 167.005,30.69 v1(167.64,31.325) 168.389,31.325 C43.1@168.656,31.058
  Bottom Layer w0.508: R66.1@166.522,34.157 166.205,34.157 165.379,34.982 165.379,36.252 166.014,36.887 166.395,36.887 167.17,37.662 C47.1@167.17,38.005
  Bottom Layer w0.635: C47.1@167.17,38.005 167.237,38.072 U8.5@167.237,39.671
  Bottom Layer w0.762: Q11.2@156.546,21.764 157.229,21.082 J4.1@159.726,21.082 ; D17.2@165.684,11.125 163.881,11.125 162.433,12.573 162.433,15.494 159.726,18.201 J4.1@159.726,21.082 ; R66.1@166.522,34.157 166.497,34.132 R47.2@166.497,32.506 167.018,32.506 167.64,31.884 v1(167.64,31.325) 167.64,25.07 165.456,22.885 161.53,22.885 J4.1@159.726,21.082
5VP: C15.2 R23.2 R32.2 U2.8 | length 5.6
  Bottom Layer w0.508: R32.2@106.626,37.663 106.626,37.838 107.332,38.545 107.332,39.224 C15.2@107.478,39.37 107.479,39.371 R23.2@107.48,40.767 R23.2@107.48,40.767 109.123,40.767 109.169,40.813 U2.8@109.169,41.236
10V_A: C35.1 C57.1 Q11.3 Q14.2 R39.2 R40.2 R42.2 R56.1 R73.1 U7.8 | length 16.5
  Top Layer w0.508: C35.1@150.571,37.129 150.694,37.252 U7.8@152.273,37.252
  Top Layer w0.635: R42.2@148.933,32.011 148.933,32.252 147.625,33.56 147.625,34.398 148.692,35.465 R56.1@148.958,35.465
  Top Layer w0.762: R42.2@148.933,32.011 R39.2@148.933,30.436 C57.1@148.933,28.861 148.933,26.886 v1(150.038,25.781) ; R56.1@148.958,35.465 R56.1@148.996,35.503 148.996,37.103 R40.2@148.971,37.129 ; R40.2@148.958,37.141 R40.2@148.971,37.129 ; C35.1@150.571,37.129 R40.2@148.971,37.129
12VS: C53.1 C54.1 C55.1 C56.1 D22.1 J3.1 Q14.3 R82.1
BLK: C21.1 R36.2 R90.1 R91.2 U2.3 | length 12.6
  Top Layer w0.635: v1(114.935,34.417) 114.935,37.592 v3(115.697,38.354)
  Bottom Layer w0.635: R90.1@113.31,33.001 113.364,32.947 115.224,32.947 R36.2@115.278,32.893 115.278,34.074 v1(114.935,34.417) ; U2.3@115.519,41.236 115.502,41.219 115.502,39.509 114.935,38.942 C21.1@114.935,38.327 114.962,38.354 v3(115.697,38.354) 116.137,38.354 116.142,38.35 116.477,38.35 R91.2@116.484,38.342
EARTH: CY1.1 CY2.2 J1.1 pad.1@31.471,1.981
FAN_OFF: Q9.1 Q13.1 R47.1 R52.2 U6.7 | length 24.9
  Top Layer w0.508: U6.7@165.735,30.065 165.735,29.362 v1(165.989,29.108) 166.112,28.986 169.439,28.986 v1(169.443,28.981)
  Bottom Layer w0.508: v1(169.443,28.981) 171.211,27.214 Q13.1@171.211,20.275
  Bottom Layer w0.635: Q9.1@160.208,31.852 160.208,30.375 160.909,29.674 164.186,29.674 164.922,30.41 R52.2@164.922,30.906 ; 165.684,30.906 165.938,30.652 165.862,30.576 165.989,30.449 v1(165.989,29.108)
  Bottom Layer w0.762: R52.2@164.922,30.906 165.684,30.906 R47.1@166.497,30.906
FAN_ON: Q10.1 R66.2 R83.2 U6.1 | length 25.8
  Top Layer w0.635: U6.1@167.005,35.315 167.46,35.77 v1(167.589,35.77)
  Bottom Layer w0.508: v1(167.589,35.77) 168.808,34.551 168.808,31.039 172.161,27.686 172.161,19.507 170.72,18.066 R83.2@170.72,16.085
  Bottom Layer w0.635: Q10.1@170.72,14.285 R83.2@170.72,16.085
  Bottom Layer w0.762: R66.2@166.522,35.757 166.535,35.77 v1(167.589,35.77)
FB: C20.1 U2.5 U3.4 | length 28.6
  Top Layer w0.635: v1(111.227,38.964) 114.391,38.964 114.953,39.526 121.739,39.526 124.276,36.989 U3.4@134.725,36.989
  Bottom Layer w0.635: C20.1@111.252,38.113 111.252,38.938 v1(111.227,38.964) 112.527,40.264 112.527,40.344 112.979,40.796 U2.5@112.979,41.236
HO: D7.2 Q16.1 U2.15 | length 89.2
  Top Layer w0.635: v2(103.886,80.137) 114.046,80.137 118.491,75.692 v2(118.491,73.66)
  Bottom Layer w0.635: D7.2@83.82,98.005 86.332,98.005 86.35,97.988 Q16.1@86.35,97.872 ; Q16.1@86.35,98.037 87.347,99.035 92.082,99.035 96.114,95.003 96.114,88.627 99.492,85.249 102.819,85.249 103.886,84.182 v2(103.886,80.137) ; U2.15@116.789,46.636 116.789,45.457 117.161,45.085 120.585,45.085 122.499,46.999 122.499,69.652 v2(118.491,73.66)
HS: C18.1 L5.3 Q7.3 Q8.2 Q16.3 R33.1 U2.16 | length 49
  Top Layer w0.635: 107.95,79.121 112.295,79.121 116.967,74.449 v2(116.967,73.66)
  Bottom Layer w0.635: Q16.3@87.3,95.472 87.3,95.307 87.317,95.29 88.284,95.29 89.136,94.437 91.669,94.437 ; L5.3@107.286,66.647 L5.3@107.339,66.647 L5.3@107.668,66.647 ; v2(116.967,73.66) 121.664,68.963 121.664,47.964 121.36,47.66 121.278,47.66 120.571,46.954 C18.1@120.421,46.954 118.077,46.954 118.059,46.936 U2.16@118.059,46.636 U2.16@118.042,46.654
IREF: C36.2 R55.2 R57.1 R58.2 R85.1 U7.5 | length 9.1
  Top Layer w0.508: U7.5@156.083,37.252 156.168,37.167 v1(156.845,37.167) 158.708,37.167 R85.1@158.801,37.074
  Bottom Layer w0.635: R55.2@156.769,35.757 156.845,35.833 v1(156.845,37.167)
  Bottom Layer w0.762: C36.2@153.568,35.757 R57.1@155.169,35.757 R55.2@156.769,35.757 158.42,35.757 R58.2@158.433,35.77
ISNS: C24.2 C28.1 R31.2 U2.9 | length 7.4
  Bottom Layer w0.635: C28.1@108.915,48.387 108.94,48.387 109.098,48.229 109.098,48.204 109.152,48.15 109.152,46.654 U2.9@109.169,46.636 U2.9@109.175,46.642 ; C28.1@109.041,48.547 109.041,50.27 R31.2@108.765,50.546 108.765,52.726 109.453,53.414 C24.2@109.728,53.414
"L Wire": F1.2 J1.3 | length 7.6
  Top Layer w0.254: J1.3@24.587,9.804 25.654,8.738 30.451,8.738 31.294,9.581 F1.2@31.42,9.581
LO: D8.2 Q17.1 U2.11 | length 67.6
  Top Layer w0.635: v2(109.728,76.962) 113.03,73.66 v2(115.062,73.66)
  Bottom Layer w0.635: D8.2@99.771,91.047 99.771,92.523 98.644,93.65 98.644,94.994 100.439,96.789 Q17.1@105.48,96.789 ; D8.2@99.898,90.913 102.362,88.449 103.803,88.449 107.975,84.277 107.975,78.791 v2@109.703,77.064 ; v2(111.76,44.958) 111.727,44.991 111.727,46.619 U2.11@111.709,46.636 111.709,54.475 115.062,57.828 v2(115.062,73.66)
"N Wire": J1.2 L1.3 RV1.2 | length 0
  Top Layer w0.254: J1.2@18.212,9.83 J1.2@18.237,9.804
NetC1_1: C1.1 CY2.1 L1.1 L2.3 | length 18
  Top Layer w0.254: L2.3@21.781,46.84 21.781,42.443 23.883,40.342 23.883,30.083 23.611,29.812
NetC1_2: C1.2 CY1.2 L1.4 L2.4 | length 31.9
  Top Layer w0.254: C1.2@8.883,40.342 10.719,40.342 ; CY1.2@9.262,23.451 9.262,24.839 14.235,29.812 15.911,29.812 L1.4@15.911,30.77 15.911,36.394 11.963,40.342 10.719,40.342 ; L2.4@10.781,46.84 10.781,40.404 10.719,40.342
NetC2_1: C2.1 L2.1 L3.1 R3.1 | length 15.3
  Top Layer w0.254: L3.1@9.757,70.461 9.493,70.196 9.493,62.592 10.781,61.303 L2.1@10.781,55.84
NetC2_2: C2.2 L2.2 L3.2 R1.2 | length 17.7
  Top Layer w0.254: L3.2@19.757,70.461 24.493,65.725 24.493,62.592 21.781,59.881 L2.2@21.781,55.84
NetC4_1: C4.1 U1.2 | length 2.7
  Bottom Layer w0.635: C4.1@50.559,53.88 50.584,53.905 U1.2@53.257,53.905
NetC5_1: C5.1 D1.1 D3.2 L4.1 L4.2 L4.3 | length 79.8
  Top Layer w0.254: D1.1@13.002,91.497 15.304,93.799 15.304,95.139 16.583,96.418 42.062,96.418 42.926,95.555 42.926,88.519 47.566,83.879 48.969,83.879 D3.2@48.997,83.852 48.997,83.352 49.632,82.717 L4.2@49.632,75.918 49.632,75.565 47.6,73.533 46.143,73.533 46.131,73.521 41.721,73.521 37.236,69.037 C5.1@34.29,69.037
  Top Layer w0.762: L4.2@49.632,75.918 L4.3@54.712,75.918
NetC5_2: C5.2 D1.4 R5.2 R7.1 | length 45.5
  Top Layer w0.254: C5.2@34.29,84.037 38.002,87.748 D1.4@38.002,91.497
  Bottom Layer w0.635: R7.1@43.282,90.605 44.806,89.081 44.806,84.944 41.148,81.287 41.148,67.259 47.822,60.586 R5.2@49.365,60.586
NetC6_1: C6.1 D2.3 R5.1 U1.3 | length 7.8
  Bottom Layer w0.635: R5.1@50.965,60.586 51.086,60.465 D2.3@51.086,58.02 51.086,55.271 50.99,55.175 U1.3@53.257,55.175
NetC7_1: C7.1 R10.1
NetC8_1: C8.1 R10.2 U1.5
NetC9_1: C9.1 R16.1 R17.2 U1.6
NetC11_1: C11.1 D3.1 D5.1 R14.2 R18.1 | length 20
  Bottom Layer w0.635: R14.2@73.891,62.11 80.317,68.536 88.548,68.536 C11.1@90.424,70.412
NetC11_2: C11.2 Q4.2 RF1.1
NetC12_1: C12.1 D6.1 R19.1 | length 4
  Bottom Layer w0.635: C12.1@68.263,53.474 68.14,53.351 D6.1@68.14,51.619 68.288,51.472 R19.1@68.288,49.587
NetC13_1: C13.1 R24.1 R25.2 U2.7 | length 7.4
  Bottom Layer w0.508: R25.2@105.791,44.031 C13.1@107.565,44.031 ; C13.1@107.569,44.077 107.569,44.035 C13.1@107.565,44.031 ; U2.7@110.439,41.236 110.439,41.711 109.685,42.465 108.711,42.465 108.537,42.291 R24.1@107.48,42.291 107.565,42.376 C13.1@107.565,44.031
NetC16_1: C16.1 R26.2 U2.4 | length 4.1
  Bottom Layer w0.635: R26.2@112.751,38.733 112.933,38.55 113.74,38.55 C16.1@113.792,38.498 113.792,39.069 114.232,39.509 114.232,41.219 U2.4@114.249,41.236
